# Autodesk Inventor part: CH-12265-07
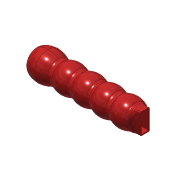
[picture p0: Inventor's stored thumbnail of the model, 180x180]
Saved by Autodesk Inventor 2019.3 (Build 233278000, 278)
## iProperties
Created: 2012-09
Part Number: CH-12265-07
Material: Ogólny
Document SubType Name: Modeling
Designer: CADENGINEERING4
Density: 1 g/cm^3
Appearance: Jasnoczerwona
Author: CADENGINEERING4
Revision Number: ÈÎºÎ
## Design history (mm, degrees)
feature "ÇÐ³ý-À­Éì1"
node "Bryła1"
